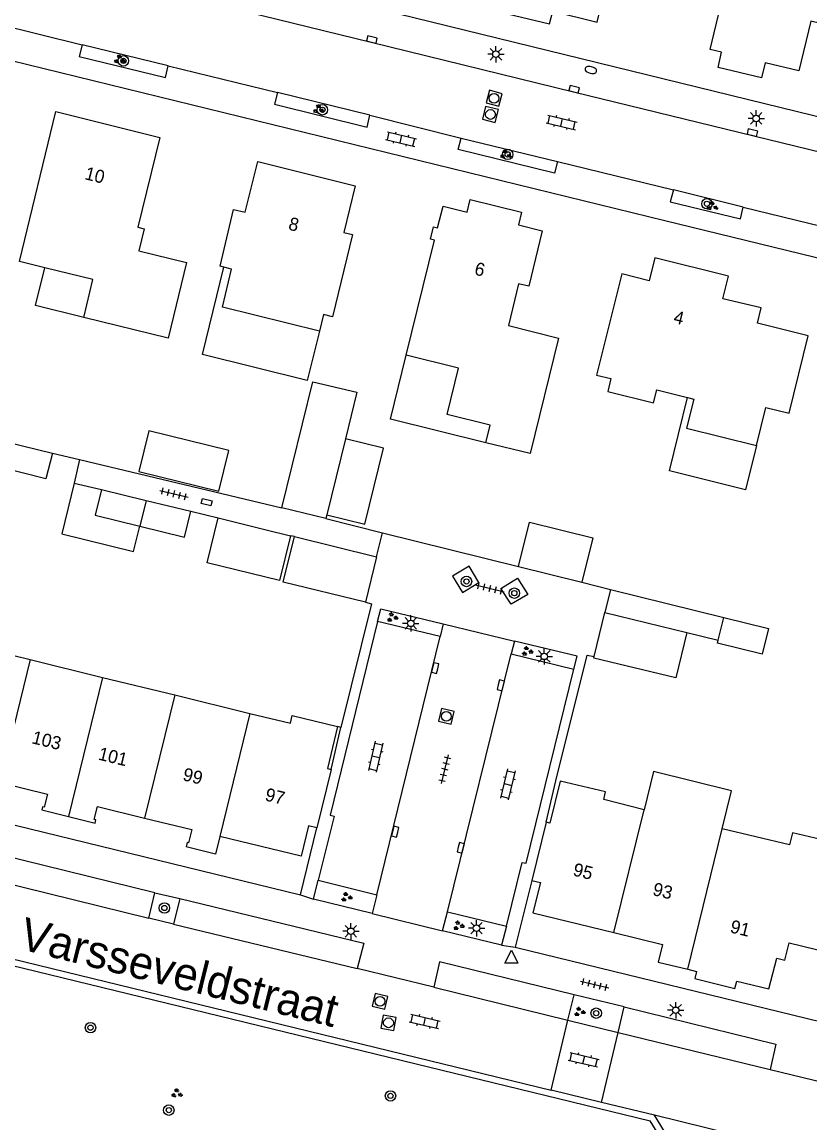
# Model space of a CAD drawing. Extents: x 125000 to 129004, y 397500 to 399008.
# Drawn here: x 126436.9 to 126497.3, y 398421 to 398505.4 of the extents above; entities that cross this region are included whole.
import ezdxf

# ---------------------------------------------------------------- set-up
doc = ezdxf.new("R2010")
doc.units = 0
for name, color, linetype in [('gg-afsc-erfafscheiding', 7, 'Continuous'), ('gg-afsc-hekwerk', 7, 'Continuous'), ('gg-anno-huisnummerreeks BGT', 7, 'Continuous'), ('gg-anno-openbare ruimte label', 7, 'Continuous'), ('gg-bbg-bijgebouw', 7, 'Continuous'), ('gg-bbg-gedigitaliseerde bijgebouw', 7, 'Continuous'), ('gg-bbg-hoofdgebouw', 7, 'Continuous'), ('gg-bbg-luifel en loopbrug', 7, 'Continuous'), ('gg-bbg-tussenscheiding', 7, 'Continuous'), ('gg-knt-verharding', 7, 'Continuous'), ('gg-knt-verharding nz', 7, 'Continuous'), ('gt-grn-weggrens', 7, 'Continuous'), ('gt-symb-boom', 7, 'Continuous'), ('gt-symb-brandkraan', 7, 'Continuous'), ('gt-symb-groenvak', 7, 'Continuous'), ('gt-symb-klinker verharding', 7, 'Continuous'), ('gt-symb-kolk', 7, 'Continuous'), ('gt-symb-kolk center center', 7, 'Continuous'), ('gt-symb-lichtmast', 7, 'Continuous'), ('gt-symb-rioolschacht', 7, 'Continuous'), ('gt-symb-tegel verharding', 7, 'Continuous'), ('gt-symb-waterafsluiter', 7, 'Continuous')]:
    doc.layers.add(name, color=color, linetype=linetype)

# ---------------------------------------------------------------- blocks, each defined once
blk = doc.blocks.new('gt0-LMAST')
at = {"layer": 'gt-symb-lichtmast'}
for p, q in [((-0.182, 0.173), (-0.447, 0.438)), ((-0.005, 0.246), (-0.005, 0.621)), ((0.172, 0.173), (0.437, 0.438)), ((-0.255, -0.004), (-0.63, -0.004)), ((-0.182, -0.181), (-0.447, -0.446)), ((-0.005, -0.254), (-0.005, -0.629)), ((0.437, -0.446), (0.172, -0.181)), ((0.245, -0.004), (0.62, -0.004))]:
    blk.add_line(p, q, dxfattribs=at)
blk.add_circle((-0.005, -0.004), 0.25, dxfattribs=at)
blk = doc.blocks.new('gt0-RS')
at = {"layer": 'gt-symb-rioolschacht'}
blk.add_lwpolyline([(-0.5, -0.5), (0.5, -0.5), (0.5, 0.5), (-0.5, 0.5)], close=True, dxfattribs=at)
blk.add_circle((0, 0), 0.375, dxfattribs=at)
blk = doc.blocks.new('gt0-BOOM')
at = {"layer": 'gt-symb-boom'}
for radius in [0.4, 0.2]:
    blk.add_circle((0, 0), radius, dxfattribs=at)
blk = doc.blocks.new('gt0-KL1')
at = {"layer": 'gt-symb-klinker verharding'}
for p, q in [((-1.15, 0.3), (1.15, 0.3)), ((-1, -0.3), (-1, 0.3)), ((-0.5, 0.3), (-0.5, 0.45)), ((0, -0.3), (0, 0.3)), ((0.5, 0.3), (0.5, 0.45)), ((1, -0.3), (1, 0.3)), ((-1.15, -0.3), (1.15, -0.3)), ((-0.5, -0.45), (-0.5, -0.3)), ((0.5, -0.45), (0.5, -0.3))]:
    blk.add_line(p, q, dxfattribs=at)
blk = doc.blocks.new('gt0-GRVAK')
at = {"layer": 'gt-symb-groenvak'}
for p, q in [((-0.11, 0.189), (-0.228, 0.24)), ((-0.182, 0.153), (0.088, 0.153)), ((-0.091, 0.211), (-0.156, 0.322)), ((-0.047, 0.214), (-0.047, 0.393)), ((-0.004, 0.211), (0.061, 0.322)), ((0.015, 0.189), (0.133, 0.24)), ((0.262, -0.052), (0.197, 0.059)), ((0.305, -0.049), (0.305, 0.13)), ((0.349, -0.052), (0.414, 0.059)), ((-0.245, -0.228), (-0.363, -0.177)), ((-0.318, -0.264), (-0.047, -0.264)), ((-0.226, -0.206), (-0.291, -0.095)), ((-0.183, -0.203), (-0.183, -0.024)), ((-0.139, -0.206), (-0.074, -0.095)), ((-0.12, -0.228), (-0.002, -0.177)), ((0.243, -0.074), (0.125, -0.023)), ((0.17, -0.11), (0.441, -0.11)), ((0.368, -0.074), (0.486, -0.023))]:
    blk.add_line(p, q, dxfattribs=at)
blk = doc.blocks.new('gt0-KOLKCC')
at = {"layer": 'gt-symb-kolk center center'}
blk.add_lwpolyline([(-0.375, 0.2), (0.375, 0.2), (0.375, -0.2), (-0.375, -0.2)], close=True, dxfattribs=at)
blk = doc.blocks.new('gt0-TEG1')
at = {"layer": 'gt-symb-tegel verharding'}
for p, q in [((-1.125, 0), (1.125, 0)), ((-0.9, -0.25), (-0.9, 0.25)), ((-0.45, -0.25), (-0.45, 0.25)), ((0, -0.25), (0, 0.25)), ((0.45, -0.25), (0.45, 0.25)), ((0.9, -0.25), (0.9, 0.25))]:
    blk.add_line(p, q, dxfattribs=at)
blk = doc.blocks.new('gt0-KOLK')
at = {"layer": 'gt-symb-kolk'}
blk.add_lwpolyline([(0, 0), (0.375, 0), (0.375, 0.4), (-0.375, 0.4), (-0.375, 0), (0, 0)], dxfattribs=at)
blk = doc.blocks.new('gt0-WAFSL')
at = {"layer": 'gt-symb-waterafsluiter'}
for p, q in [((-0.5, -0.333), (0, 0.667)), ((0, 0.667), (0.5, -0.333)), ((0.5, -0.333), (-0.5, -0.333))]:
    blk.add_line(p, q, dxfattribs=at)
blk = doc.blocks.new('gt0-BR')
at = {"layer": 'gt-symb-brandkraan'}
for centre, radius, start, end in [((-0.244, 0), 0.206, 107.56694, 252.43307), ((0.599, -2.664), 3, 106.89205, 107.56694), ((0, -0.691), 0.938, 73.10799, 106.89205), ((-0.599, -2.664), 3, 72.43309, 73.10799), ((0.244, 0), 0.206, 287.56695, 72.43309), ((0.599, 2.664), 3, 252.43307, 253.10797), ((0, 0.691), 0.938, 253.10797, 286.89206), ((-0.599, 2.664), 3, 286.89206, 287.56695)]:
    blk.add_arc(centre, radius, start, end, dxfattribs=at)

msp = doc.modelspace()

# ---------------------------------------------------------------- linework, layer by layer
at = {"layer": 'gg-afsc-erfafscheiding'}
for p, q in [((126439.249, 398472.358), (126441.34, 398471.876)), ((126441.34, 398471.876), (126440.921, 398470.058)), ((126487.84, 398458.616), (126490.248, 398458.033))]:
    msp.add_line(p, q, dxfattribs=at)
at = {"layer": 'gg-afsc-hekwerk'}
for p, q in [((126449.852, 398467.895), (126451.958, 398467.384)), ((126460.202, 398467.332), (126464.536, 398466.255)), ((126464.536, 398466.255), (126474.948, 398463.668)), ((126457.788, 398465.956), (126457.491, 398466.013)), ((126479.8, 398462.462), (126482.004, 398461.914)), ((126482.004, 398461.914), (126490.678, 398459.759)), ((126474.651, 398457.938), (126474.401, 398456.967)), ((126461.354, 398451.34), (126461.092, 398451.404))]:
    msp.add_line(p, q, dxfattribs=at)
for points in [[(126463.223, 398460.932), (126463.699, 398460.815), (126461.354, 398451.34)], [(126479.188, 398455.795), (126479.444, 398456.787), (126474.651, 398457.938)], [(126477.822, 398447.256), (126480.206, 398456.866), (126480.745, 398456.769)]]:
    msp.add_lwpolyline(points, dxfattribs=at)
at = {"layer": 'gg-bbg-bijgebouw'}
for p, q in [((126461.703, 398473.451), (126460.273, 398467.623)), ((126443.022, 398469.574), (126446.437, 398468.735)), ((126446.437, 398468.735), (126449.852, 398467.895)), ((126460.202, 398467.332), (126456.832, 398468.158)), ((126460.273, 398467.623), (126460.202, 398467.332)), ((126455.521, 398466.501), (126457.491, 398466.013)), ((126457.788, 398465.956), (126464.078, 398464.411)), ((126464.078, 398464.411), (126463.223, 398460.932)), ((126480.745, 398456.769), (126481.562, 398460.137)), ((126481.562, 398460.137), (126487.84, 398458.616)), ((126490.248, 398458.033), (126490.678, 398459.759))]:
    msp.add_line(p, q, dxfattribs=at)
for points in [[(126456.832, 398468.158), (126459.202, 398477.822), (126462.576, 398477.011), (126461.703, 398473.451)], [(126439.249, 398472.358), (126438.762, 398470.387), (126435.33, 398471.239), (126435.823, 398473.204), (126439.249, 398472.358)], [(126443.022, 398469.574), (126442.537, 398467.603), (126445.952, 398466.764)], [(126445.952, 398466.764), (126449.367, 398465.924), (126449.852, 398467.895)], [(126463.223, 398460.932), (126456.934, 398462.477), (126457.788, 398465.956)], [(126490.678, 398459.759), (126494.112, 398458.911), (126493.626, 398456.941), (126490.187, 398457.79), (126490.248, 398458.033)], [(126487.84, 398458.616), (126486.996, 398455.131), (126480.717, 398456.653), (126480.745, 398456.769)]]:
    msp.add_lwpolyline(points, dxfattribs=at)
at = {"layer": 'gg-bbg-gedigitaliseerde bijgebouw'}
msp.add_line((126451.958, 398467.384), (126455.521, 398466.501), dxfattribs=at)
msp.add_lwpolyline([(126457.491, 398466.013), (126456.642, 398462.587), (126451.11, 398463.957), (126451.958, 398467.384)], dxfattribs=at)
at = {"layer": 'gg-bbg-hoofdgebouw'}
for p, q in [((126466.353, 398479.86), (126468.519, 398488.659)), ((126459.709, 398481.706), (126452.281, 398483.536)), ((126432.005, 398457.893), (126437.552, 398456.536)), ((126437.552, 398456.536), (126443.082, 398455.173)), ((126443.082, 398455.173), (126448.623, 398453.828)), ((126448.623, 398453.828), (126454.381, 398452.417)), ((126460.595, 398448.123), (126459.507, 398443.635)), ((126477.07, 398444.078), (126475.983, 398439.612))]:
    msp.add_line(p, q, dxfattribs=at)
for points in [[(126475.782, 398517.478), (126473.218, 398507.277), (126474.359, 398506.995), (126474.123, 398506.013), (126477.334, 398505.242), (126477.578, 398506.199), (126480.968, 398505.374), (126483.031, 398513.722), (126485.829, 398513.111), (126487.589, 398520.262)], [(126499.181, 398512.968), (126498.369, 398509.632), (126499.094, 398509.456), (126498.075, 398505.269), (126497.35, 398505.446), (126496.422, 398501.636), (126493.858, 398502.241), (126493.571, 398501.094), (126490.253, 398501.902), (126490.509, 398503.069), (126489.646, 398503.266), (126490.436, 398506.568), (126489.462, 398506.831)], [(126438.67, 398486.555), (126436.726, 398487.027), (126439.514, 398498.513)], [(126439.514, 398498.513), (126447.479, 398496.539), (126445.793, 398489.663), (126446.279, 398489.546), (126445.871, 398487.847), (126449.537, 398486.948), (126448.118, 398481.159), (126441.654, 398482.744)], [(126452.392, 398486.594), (126452.1, 398486.663), (126453.138, 398491.026), (126454.021, 398490.81), (126454.985, 398494.692), (126462.45, 398492.839), (126461.567, 398489.261), (126462.247, 398489.093), (126460.697, 398482.804), (126460.021, 398482.971), (126459.709, 398481.706)], [(126468.519, 398488.659), (126468.218, 398488.733), (126468.451, 398489.675), (126468.761, 398489.598), (126469.172, 398491.258), (126471.017, 398490.802), (126471.255, 398491.773), (126475.183, 398490.811), (126474.947, 398489.844), (126476.779, 398489.374), (126475.757, 398485.137), (126474.95, 398485.332), (126474.185, 398482.119), (126478.011, 398481.158), (126475.849, 398472.314), (126472.465, 398473.147)], [(126493.174, 398472.946), (126493.892, 398475.857), (126495.677, 398475.416), (126497.138, 398481.335), (126493.268, 398482.295), (126493.549, 398483.472), (126490.607, 398484.173), (126491.04, 398485.91), (126485.406, 398487.314), (126484.953, 398485.561), (126482.857, 398486.083), (126480.926, 398478.336)], [(126441.654, 398482.744), (126442.362, 398485.659), (126438.67, 398486.555)], [(126452.281, 398483.536), (126452.976, 398486.455), (126452.392, 398486.594)], [(126472.465, 398473.147), (126472.796, 398474.489), (126469.49, 398475.303), (126470.368, 398478.871), (126466.353, 398479.86)], [(126480.926, 398478.336), (126482.032, 398478.063), (126481.79, 398477.083), (126485.303, 398476.216), (126485.545, 398477.196), (126487.899, 398476.615)], [(126487.899, 398476.615), (126488.378, 398476.497), (126487.827, 398474.265), (126493.174, 398472.946)], [(126454.381, 398452.417), (126457.485, 398451.66), (126457.627, 398452.244), (126461.092, 398451.404)], [(126461.092, 398451.404), (126460.313, 398448.191), (126460.595, 398448.123)], [(126490.554, 398443.574), (126491.269, 398446.487), (126485.299, 398447.953), (126484.582, 398445.039)], [(126435.247, 398447.114), (126438.874, 398446.222), (126438.629, 398445.225), (126438.498, 398445.257), (126438.438, 398445.014), (126440.482, 398444.514)], [(126484.582, 398445.039), (126481.485, 398445.816), (126481.623, 398446.4), (126478.145, 398447.225), (126477.352, 398444.009), (126477.07, 398444.078)], [(126440.482, 398444.514), (126442.526, 398444.014), (126442.585, 398444.257), (126442.454, 398444.289), (126442.697, 398445.283), (126446.316, 398444.399)], [(126446.316, 398444.399), (126449.935, 398443.514), (126449.69, 398442.509), (126449.583, 398442.536), (126449.5, 398442.196)], [(126459.507, 398443.635), (126458.866, 398443.79), (126458.301, 398441.468), (126452.079, 398442.98)], [(126499.423, 398442.451), (126495.931, 398443.276), (126495.699, 398442.339), (126490.554, 398443.574)], [(126452.079, 398442.98), (126451.748, 398441.64), (126449.5, 398442.196)], [(126475.983, 398439.612), (126476.629, 398439.467), (126476.058, 398437.146), (126482.267, 398435.62)], [(126482.267, 398435.62), (126485.988, 398434.705), (126485.662, 398433.364), (126487.936, 398432.811)], [(126487.936, 398432.811), (126488.585, 398432.653), (126488.45, 398432.099), (126491.527, 398431.35), (126491.679, 398431.905), (126494.136, 398431.311), (126494.73, 398433.654), (126495.362, 398433.502), (126495.682, 398434.829), (126499.761, 398433.837)]]:
    msp.add_lwpolyline(points, dxfattribs=at)
at = {"layer": 'gg-bbg-luifel en loopbrug'}
for p, q in [((126440.921, 398470.058), (126443.022, 398469.574)), ((126474.948, 398463.668), (126479.8, 398462.462))]:
    msp.add_line(p, q, dxfattribs=at)
for points in [[(126441.654, 398482.744), (126437.956, 398483.654), (126438.67, 398486.555)], [(126459.709, 398481.706), (126458.779, 398477.926), (126450.745, 398479.904), (126452.392, 398486.594)], [(126472.465, 398473.147), (126465.144, 398474.949), (126466.353, 398479.86)], [(126493.174, 398472.946), (126492.336, 398469.548), (126486.51, 398470.985), (126487.899, 398476.615)], [(126452.001, 398469.45), (126452.766, 398472.557), (126446.648, 398474.063), (126445.883, 398470.956), (126452.001, 398469.45)], [(126460.273, 398467.623), (126463.187, 398466.909), (126464.616, 398472.736), (126461.703, 398473.451)], [(126440.921, 398470.058), (126439.965, 398466.174), (126445.473, 398464.818), (126445.952, 398466.764)], [(126474.948, 398463.668), (126475.786, 398467.066), (126480.641, 398465.869), (126479.8, 398462.462)]]:
    msp.add_lwpolyline(points, dxfattribs=at)
at = {"layer": 'gg-bbg-tussenscheiding'}
for p, q in [((126446.437, 398468.735), (126445.952, 398466.764)), ((126437.552, 398456.536), (126435.247, 398447.114)), ((126443.082, 398455.173), (126440.482, 398444.514)), ((126448.623, 398453.828), (126446.316, 398444.399)), ((126454.381, 398452.417), (126452.079, 398442.98)), ((126482.267, 398435.62), (126484.582, 398445.039)), ((126487.936, 398432.811), (126490.554, 398443.574))]:
    msp.add_line(p, q, dxfattribs=at)
at = {"layer": 'gg-knt-verharding'}
for p, q in [((126448.121, 398502.023), (126441.531, 398503.636)), ((126463.579, 398498.229), (126456.489, 398499.968)), ((126470.57, 398496.479), (126477.943, 398494.685)), ((126492.151, 398491.188), (126486.833, 398492.512)), ((126441.34, 398471.876), (126456.832, 398468.158)), ((126468.957, 398458.309), (126464.167, 398459.466)), ((126469.176, 398459.267), (126468.957, 398458.309)), ((126464.115, 398438.511), (126468.957, 398458.309)), ((126469.523, 398437.201), (126474.401, 398456.967)), ((126474.401, 398456.967), (126479.188, 398455.795)), ((126460.595, 398448.123), (126461.354, 398451.34)), ((126477.07, 398444.078), (126477.822, 398447.256)), ((126458.257, 398438.513), (126459.507, 398443.635)), ((126459.243, 398438.179), (126459.602, 398439.637)), ((126459.602, 398439.637), (126464.115, 398438.511)), ((126475.983, 398439.612), (126474.689, 398434.517)), ((126446.639, 398436.74), (126447.089, 398438.676)), ((126447.089, 398438.676), (126449.027, 398438.232)), ((126464.115, 398438.511), (126463.755, 398437.075)), ((126449.027, 398438.232), (126448.536, 398436.271)), ((126463.755, 398437.075), (126459.243, 398438.179)), ((126422.515, 398436.946), (126477.448, 398423.561)), ((126448.536, 398436.271), (126446.639, 398436.74)), ((126469.144, 398435.746), (126469.523, 398437.201)), ((126469.523, 398437.201), (126474.034, 398436.111)), ((126422.597, 398436.411), (126485.043, 398421.203)), ((126474.034, 398436.111), (126473.659, 398434.658)), ((126473.659, 398434.658), (126469.144, 398435.746)), ((126474.689, 398434.517), (126515.08, 398424.64)), ((126468.457, 398431.438), (126462.585, 398432.884)), ((126478.734, 398428.921), (126479.22, 398430.865)), ((126483.043, 398429.933), (126479.22, 398430.865)), ((126482.6, 398427.959), (126483.043, 398429.933)), ((126477.448, 398423.561), (126478.734, 398428.921)), ((126478.734, 398428.921), (126482.6, 398427.959)), ((126481.32, 398422.617), (126482.6, 398427.959)), ((126494.232, 398425.132), (126503.479, 398422.878)), ((126481.32, 398422.617), (126477.448, 398423.561)), ((126485.361, 398421.64), (126481.32, 398422.617))]:
    msp.add_line(p, q, dxfattribs=at)
for points in [[(126534.627, 398482.986), (126524.37, 398491.638), (126387.926, 398525.085), (126386.968, 398525.335)], [(126384.443, 398515.102), (126397.312, 398511.963), (126486.151, 398490.174), (126519.449, 398482.042), (126523.671, 398478.485)], [(126441.531, 398503.636), (126441.299, 398502.742), (126447.911, 398501.124), (126448.121, 398502.023)], [(126456.489, 398499.968), (126456.267, 398499.078), (126463.352, 398497.326), (126463.579, 398498.229)], [(126477.943, 398494.685), (126477.721, 398493.793), (126470.341, 398495.605), (126470.57, 398496.479)], [(126486.833, 398492.512), (126486.583, 398491.602), (126491.947, 398490.304), (126492.151, 398491.188)], [(126469.907, 398462.931), (126470.658, 398461.682), (126471.926, 398462.441), (126471.169, 398463.689), (126469.907, 398462.931)], [(126474.879, 398462.781), (126475.666, 398461.526), (126474.396, 398460.776), (126473.607, 398461.988), (126474.879, 398462.781)], [(126464.167, 398459.466), (126464.411, 398460.435), (126469.176, 398459.267)], [(126464.167, 398459.466), (126460.524, 398444.627), (126460.823, 398444.533), (126459.602, 398439.637)], [(126373.12, 398459.365), (126422.146, 398447.329), (126458.257, 398438.513)], [(126474.034, 398436.111), (126475.231, 398441.004), (126475.548, 398440.938), (126479.188, 398455.795)], [(126447.089, 398438.676), (126423.332, 398444.518), (126422.857, 398442.554)], [(126449.027, 398438.232), (126463.098, 398434.809), (126462.585, 398432.884)], [(126479.22, 398430.865), (126468.915, 398433.384), (126468.457, 398431.438)], [(126483.043, 398429.933), (126494.675, 398427.077), (126494.232, 398425.132)], [(126487.47, 398412.291), (126488.506, 398416.512), (126485.361, 398421.64)], [(126486.866, 398411.927), (126487.971, 398416.429), (126485.043, 398421.203)]]:
    msp.add_lwpolyline(points, dxfattribs=at)
at = {"layer": 'gg-knt-verharding nz'}
for p, q in [((126434.628, 398505.339), (126441.531, 398503.636)), ((126448.121, 398502.023), (126456.489, 398499.968)), ((126463.579, 398498.229), (126470.57, 398496.479)), ((126477.943, 398494.685), (126486.833, 398492.512)), ((126492.151, 398491.188), (126499.287, 398489.462)), ((126422.857, 398442.554), (126446.639, 398436.74)), ((126448.536, 398436.271), (126462.585, 398432.884)), ((126468.457, 398431.438), (126478.734, 398428.921)), ((126482.6, 398427.959), (126494.232, 398425.132))]:
    msp.add_line(p, q, dxfattribs=at)
msp.add_lwpolyline([(126388.129, 398522.392), (126405.708, 398518.092), (126433.707, 398511.188), (126463.681, 398503.845), (126479.173, 398500.034), (126522.795, 398489.385)], dxfattribs=at)
at = {"layer": 'gt-grn-weggrens'}
for p, q in [((126464.078, 398464.411), (126464.536, 398466.255)), ((126482.004, 398461.914), (126481.562, 398460.137)), ((126469.176, 398459.267), (126474.651, 398457.938)), ((126458.257, 398438.513), (126459.243, 398438.179)), ((126463.755, 398437.075), (126469.144, 398435.746)), ((126473.659, 398434.658), (126474.689, 398434.517)), ((126497.151, 398418.745), (126485.361, 398421.64))]:
    msp.add_line(p, q, dxfattribs=at)

# ---------------------------------------------------------------- block references
at = {"layer": 'gt-symb-boom'}
for p in [(126444.694, 398502.4), (126459.936, 398498.653), (126474.124, 398495.236), (126489.389, 398491.456), (126470.968, 398462.521), (126474.636, 398461.625), (126447.832, 398437.508), (126480.907, 398429.45), (126442.172, 398428.338), (126465.149, 398423.111), (126448.169, 398422.023)]:
    msp.add_blockref('gt0-BOOM', p, dxfattribs=at)
at = {"layer": 'gt-symb-brandkraan', "rotation": -13.772145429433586}
msp.add_blockref('gt0-BR', (126480.499, 398501.697), dxfattribs=at)
at = {"layer": 'gt-symb-groenvak'}
for p, rotation in [((126444.388, 398502.503), -13.411071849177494), ((126459.635, 398498.692), -13.466776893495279), ((126473.958, 398495.226), -13.411071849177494), ((126489.783, 398491.261), -13.480126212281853), ((126448.777, 398423.293), -13.411071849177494)]:
    msp.add_blockref('gt0-GRVAK', p, dxfattribs=dict(at, rotation=rotation))
for p in [(126465.277, 398459.767), (126475.609, 398457.169), (126461.771, 398438.336), (126470.354, 398436.151), (126479.618, 398429.548)]:
    msp.add_blockref('gt0-GRVAK', p, dxfattribs=at)
at = {"layer": 'gt-symb-klinker verharding'}
for p, rotation in [((126478.264, 398497.686), -13.299584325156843), ((126465.96, 398496.407), -13.299584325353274), ((126464.015, 398449.094), -103.35534096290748), ((126474.14, 398446.972), -103.35534096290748), ((126467.769, 398428.822), -13.299584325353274), ((126479.954, 398425.886), -13.355340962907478)]:
    msp.add_blockref('gt0-KL1', p, dxfattribs=dict(at, rotation=rotation))
at = {"layer": 'gt-symb-kolk'}
for p, rotation in [((126463.681, 398503.845), -13.77214543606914), ((126479.173, 398500.034), -13.82779503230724), ((126492.824, 398496.708), -13.702889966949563), ((126468.764, 398455.835), 76.17220496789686), ((126473.407, 398454.609), -103.95282331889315), ((126465.7, 398443.309), 76.29711003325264), ((126470.336, 398442.164), -103.82779503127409)]:
    msp.add_blockref('gt0-KOLK', p, dxfattribs=dict(at, rotation=rotation))
at = {"layer": 'gt-symb-kolk center center', "rotation": -14.300277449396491}
msp.add_blockref('gt0-KOLKCC', (126451.074, 398468.593), dxfattribs=at)
at = {"layer": 'gt-symb-lichtmast'}
for p in [(126473.233, 398502.911), (126493.166, 398497.997), (126466.709, 398459.316), (126476.933, 398456.784), (126462.121, 398435.728), (126471.745, 398435.964), (126486.999, 398429.674)]:
    msp.add_blockref('gt0-LMAST', p, dxfattribs=at)
at = {"layer": 'gt-symb-rioolschacht'}
for p, rotation in [((126473.082, 398499.532), 165.0464352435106), ((126472.808, 398498.295), 166.51987378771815), ((126469.432, 398452.188), -103.88341803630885), ((126464.351, 398430.36), -103.29958432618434), ((126464.998, 398428.712), -100.25359802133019)]:
    msp.add_blockref('gt0-RS', p, dxfattribs=dict(at, rotation=rotation))
at = {"layer": 'gt-symb-tegel verharding'}
for p, rotation in [((126448.566, 398469.234), -13.424370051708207), ((126472.766, 398461.993), -13.64723833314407), ((126469.304, 398448.148), -103.41107184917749), ((126480.787, 398431.645), -13.411071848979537)]:
    msp.add_blockref('gt0-TEG1', p, dxfattribs=dict(at, rotation=rotation))
at = {"layer": 'gt-symb-waterafsluiter'}
msp.add_blockref('gt0-WAFSL', (126474.406, 398433.613), dxfattribs=at)

# ---------------------------------------------------------------- texts
at = {"layer": 'gg-anno-huisnummerreeks BGT'}
for s, rotation, p in [('10', 346.1, (126441.671, 398493.343)), ('8', 346.1, (126457.269, 398489.488)), ('6', 346.1, (126471.517, 398486.041)), ('4', 346, (126486.767, 398482.337)), ('103', 346.2, (126437.618, 398450.134)), ('101', 346.3, (126442.702, 398448.884)), ('99', 346.2, (126449.173, 398447.304)), ('97', 346.4, (126455.476, 398445.756)), ('95', 346.2, (126479.064, 398440.01)), ('93', 346.2, (126485.165, 398438.51)), ('91', 346.4, (126491.104, 398435.646))]:
    msp.add_text(s, height=1, rotation=rotation, dxfattribs=at).set_placement(p)
at = {"layer": 'gg-anno-openbare ruimte label'}
msp.add_text('Varsseveldstraat', height=2.5, rotation=346, dxfattribs=at).set_placement((126436.603, 398434.395))

doc.saveas('drawing.dxf')
